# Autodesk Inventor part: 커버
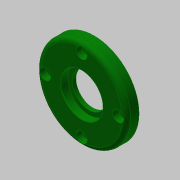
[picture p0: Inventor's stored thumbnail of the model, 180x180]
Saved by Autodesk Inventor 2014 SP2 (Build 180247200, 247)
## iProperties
Created: 2019-09
Part Number: 커버
Material: 알루미늄 6061
Document SubType Name: Modeling
Designer: mduedu
Density: 1 g/cm^3
Appearance: 진녹색
Author: mduedu
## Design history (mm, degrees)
sketch "스케치1"
  geometry: C1 r 32 at (0, 0); 1 further point
  constraints: 1 centre point, 1 coincident
  dimensions: "d0" = 64 diameter of C1
extrude "돌출1" new body sketch "스케치1" distance "d1" = 9; taper "d2" = 0 deg
sketch "스케치2"
  geometry: C1 r 21 at (0, 0); 1 further point
  constraints: 1 centre point, 1 coincident
  dimensions: "d3" = 42 diameter of C1
extrude "돌출2" join sketch "스케치2" distance "d4" = 3; taper "d5" = 0 deg
hole "구멍1" diameter "d8" = 24; stored, may be unused: countersink angle "d12" = 90 deg, drill point angle "d14" = 118 deg; dims "d6" = 10, "d7" = 10, "d9" = 6, "d10" = 30, "d11" = 5.2, "d13" = 8
hole "구멍2" diameter "d17" = 37; stored, may be unused: countersink angle "d21" = 90 deg, drill point angle "d23" = 0 deg; dims "d15" = 10, "d16" = 10, "d18" = 6, "d19" = 30, "d20" = 5.2, "d22" = 4
fillet "모깎기1" dims "d24" = 3
fillet "모깎기2" dims "d25" = 3
chamfer "모따기1" distance "d27" = 0.5; stored, may be unused: second distance "d28" = 2, angle "d29" = 30 deg
chamfer "모따기2" distance "d30" = 1; stored, may be unused: second distance "d31" = 2, angle "d32" = 30 deg
sketch "스케치3" dims "d33" = 52
  geometry: 3 further points
  constraints: 2 vertical alignment, 1 coincident, 2 other
hole "구멍3" sketch "스케치3" at (0, 26) diameter "d34" = 4.5; stored, may be unused: countersink angle "d38" = 90 deg, drill point angle "d40" = 0 deg; dims "d35" = 6, "d36" = 8, "d37" = 4.4, "d39" = 4
node "솔리드1"
pattern_circular "원형 패턴1" dims angle "d42" = 360 deg
